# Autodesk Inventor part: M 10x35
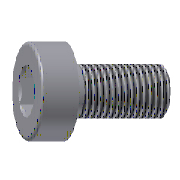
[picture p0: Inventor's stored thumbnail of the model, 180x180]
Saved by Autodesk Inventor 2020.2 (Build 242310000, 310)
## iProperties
Manager: www.cadconsulting.pl
Company: Fabian Stasiak CAD Consulting
IsCustomPart: 0
Created: 2014-02
Part Number: M 10x35
Material: Stal, miękka
Description: Socket Head Cap Screw DIN 912 - 12.9
Document SubType Name: Modeling
Designer: F.Stasiak
Standard Revision: 1
Manufacturer: DME
Language: pl-PL
Size Designation: 10x35
Categories: <MemberInstance><Categories><Category DisplayName="Forma wtryskowa" InternalName="349578f2-f4d4-4954-8c09-8e99297a61c0" Mnemonic="MOLD"><Category DisplayName="C
Mass: 0.133121 g
Surface Area: 2.01441 cm^2
Volume: 0.133121 cm^3
Density: 7.85 g/cm^3
Appearance: Częściowo polerowana
Catalog Web Link: www.expertbooks.pl
Author: F.Stasiak
Subject: Zbiór ćwiczeń. Autodesk Inventor 2020. Kurs Professional
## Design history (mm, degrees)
sketch "Sketch1"
  geometry: L1 (0, -44)-(0, 19) reference; L2 (4.619, 10)-(8, 10); L3 (8, 10)-(8, 0); L4 (8, 0)-(5, 0); L5 (5, 0)-(5, -35); L6 (5, -35)-(0, -35); L7 (0, 2.597)-(0, -35); L8 (0, 2.597)-(4, 5); L9 (4, 5)-(4, 9.381); L10 (4, 9.381)-(4.619, 10); 1 further point
  constraints: 18 end point, 4 vertical, 3 horizontal, 2 point on line
  dimensions: "d0" = 16 diameter of L3 L1 (= dk); "d1" = 10 distance between parallel lines of L4 L2 (= k); "d2" = 10 diameter of L5 L1 (= d); "d3" = 35 distance between parallel lines of L6 L4 (= L); "d4" = 59 deg angle of L1 L8; "d5" = 45 deg angle of L1 L10; "d6" = 8 diameter of L9 L1 (= sw); "d7" = 9.2376 diameter of L2.start L1 (= 1.1547 x sw); "d8" = 5 distance from line of L8.end L2 (= t)
revolve "Revolution1" sketch "Sketch1" stored, may be unused: angle "d44" = 90 deg
sketch "Sketch2"
  geometry: L1 (0, 4.619)-(4, 2.309); L2 (4, 2.309)-(4, -2.309); L3 (4, -2.309)-(0, -4.619); L4 (0, -4.619)-(-4, -2.309); L5 (-4, -2.309)-(-4, 2.309); L6 (-4, 2.309)-(0, 4.619); 3 further points
  constraints: 12 end point, 2 vertical alignment, 1 coincident, 14 other
extrude "Extrusion1" cut sketch "Sketch2" taper "d9" = 0 deg; stored distance "d45" = 10
thread "Thread1" dims "d10" = 25 (= b), "d11" = 0
chamfer "Chamfer1" distance "d12" = 0.75 (= 0.5 x P); stored, may be unused: second distance "d50" = 2, angle "d51" = 45 deg
fillet "Fillet1" dims "d13" = 0.75 (= 0.5 x P)
body "Solid1"
other parameters: "d" = 10 [user parameter; used in 1 equation term], "L" = 35 [user parameter; used in 1 equation term], "dk" = 16 [user parameter; used in 1 equation term], "b" = 25 [user parameter; used in 1 equation term], "k" = 10 [user parameter; used in 1 equation term], "sw" = 8 [user parameter; used in 2 equation terms], "t" = 5 [user parameter; used in 1 equation term], "P" = 1.5 [user parameter; used in 2 equation terms], "d14" = 0, "d15" = 0, "d55" = 0
